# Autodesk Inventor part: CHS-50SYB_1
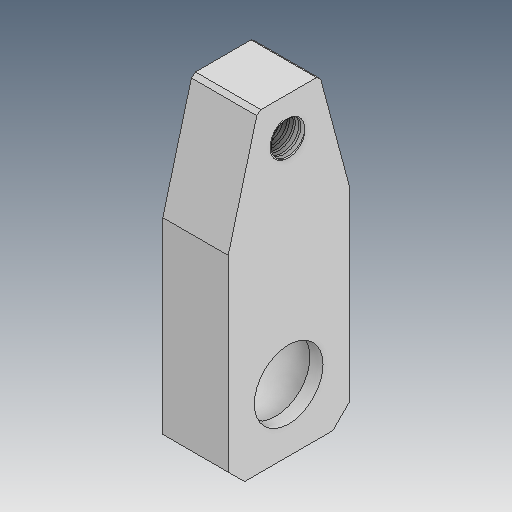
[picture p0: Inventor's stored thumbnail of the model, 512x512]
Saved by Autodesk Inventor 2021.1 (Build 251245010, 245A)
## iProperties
Created: 2019-04
Part Number: CHS-50SYB_1
Material: Ogólny
Document SubType Name: Modeling
Designer: user
Density: 1 g/cm^3
Appearance: Domyślna
Author: user
Revision Number: ÈÎºÎ
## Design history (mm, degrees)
feature "ÊäÈë1"
node "Bryła1"
